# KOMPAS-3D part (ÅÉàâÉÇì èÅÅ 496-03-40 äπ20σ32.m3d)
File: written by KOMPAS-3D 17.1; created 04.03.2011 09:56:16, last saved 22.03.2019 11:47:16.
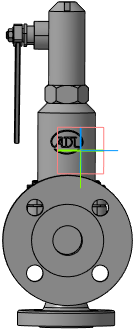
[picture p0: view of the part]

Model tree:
1. Плоскость XY
2. Плоскость ZX
3. Плоскость ZY
4. Ось X
5. Ось Y
6. Ось Z
7. Начало координат
8. Операция без истории:2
